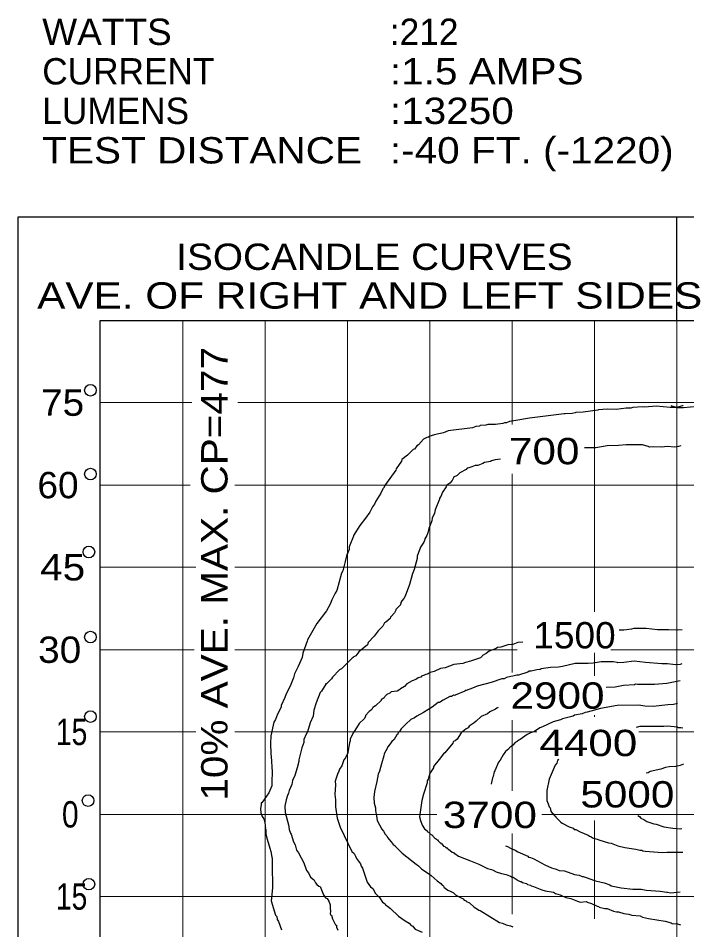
# Model space of a CAD drawing. Extents: x -39.6 to 16.1, y -17.6 to 34.
# Drawn here: x 8.955 to 11.491, y 21.539 to 25 of the extents above; entities that cross this region are included whole.
import ezdxf
from ezdxf.enums import TextEntityAlignment as Align

# ---------------------------------------------------------------- set-up
doc = ezdxf.new("R2010")
doc.units = 0
doc.header["$LTSCALE"] = 0.05
doc.layers.add('1', color=7, linetype='Continuous', lineweight=13)

msp = doc.modelspace()

# ---------------------------------------------------------------- linework, layer by layer
at = {"layer": '1', "lineweight": 25}
for p, q in [((8.95479, 19.45842), (8.95479, 24.24542)), ((8.95479, 24.24542), (13.95379, 24.24542)), ((11.45379, 23.85242), (11.45379, 24.24542)), ((9.26579, 19.78942), (9.26579, 23.85242)), ((9.26579, 23.85242), (13.95379, 23.85242))]:
    msp.add_line(p, q, dxfattribs=at)
at = {"layer": '1'}
for p, q in [((9.57879, 19.78942), (9.57879, 23.85242)), ((9.89179, 19.78942), (9.89179, 23.85242)), ((10.20379, 19.78942), (10.20379, 23.85242)), ((10.51679, 19.78942), (10.51679, 23.85242)), ((10.82879, 23.45742), (10.82879, 23.85242)), ((11.14179, 22.74642), (11.14179, 23.85242)), ((11.45379, 19.78942), (11.45379, 23.85242)), ((9.26579, 23.54042), (9.61279, 23.54042)), ((9.78779, 23.54042), (13.95379, 23.54042)), ((10.82879, 22.51542), (10.82879, 23.27042)), ((9.26579, 23.22742), (9.60679, 23.22742)), ((9.77679, 23.22742), (13.42879, 23.22742)), ((9.26579, 22.91542), (9.62879, 22.91542)), ((9.77679, 22.91542), (13.44479, 22.91542)), ((9.26579, 22.60242), (9.62279, 22.60242)), ((9.77679, 22.60242), (10.84779, 22.60242)), ((11.20379, 22.60242), (13.43979, 22.60242)), ((11.14179, 22.50342), (11.14179, 22.59042)), ((10.82879, 22.06642), (10.82879, 22.33542)), ((11.14179, 22.34742), (11.14179, 22.35342)), ((9.26579, 22.29042), (9.62879, 22.29042)), ((9.77679, 22.29042), (10.92279, 22.29042)), ((11.30979, 22.29042), (13.42879, 22.29042)), ((9.26579, 21.97742), (10.54279, 21.97742)), ((10.94179, 21.97742), (13.43979, 21.97742)), ((11.14179, 21.58042), (11.14179, 21.95442)), ((10.82879, 21.59842), (10.82879, 21.90442)), ((9.26579, 21.66542), (13.43979, 21.66542))]:
    msp.add_line(p, q, dxfattribs=at)
at = {"layer": '1', "lineweight": 25}
for points in [[(11.47579, 23.53042), (11.47479, 23.52842), (11.45179, 23.52242), (11.42879, 23.52142), (11.37579, 23.52742), (11.33179, 23.52342), (11.32279, 23.52442), (11.28679, 23.52142), (11.27879, 23.51942), (11.26179, 23.51942), (11.22279, 23.51442), (11.18879, 23.51542), (11.15579, 23.51342), (11.15379, 23.51142), (11.09779, 23.50442), (11.07079, 23.50342), (11.06779, 23.50142), (11.05679, 23.49942), (11.02979, 23.49842), (11.02579, 23.49742), (10.89479, 23.48142), (10.84279, 23.47242), (10.81879, 23.46942), (10.80679, 23.46442), (10.79979, 23.46442), (10.79379, 23.46142), (10.76579, 23.45742), (10.73679, 23.45742), (10.72879, 23.45442), (10.70679, 23.45342), (10.70479, 23.45142), (10.69079, 23.44942), (10.67879, 23.44542), (10.58579, 23.43342), (10.56779, 23.42642), (10.53279, 23.41842), (10.53079, 23.41642), (10.51679, 23.41342), (10.51079, 23.40942), (10.50479, 23.40842), (10.49179, 23.40142), (10.47379, 23.38042), (10.46679, 23.37642), (10.45779, 23.36442), (10.45379, 23.36242), (10.43179, 23.34142), (10.41079, 23.32442), (10.40879, 23.31842), (10.38879, 23.28942), (10.38779, 23.28442), (10.34779, 23.22942), (10.34079, 23.21542), (10.33779, 23.21342), (10.33079, 23.19642), (10.31179, 23.16642), (10.30679, 23.15542), (10.29879, 23.14542), (10.28879, 23.12442), (10.27179, 23.10142), (10.25079, 23.07342), (10.22679, 23.03642), (10.22679, 23.03342), (10.21079, 22.99242), (10.20979, 22.98342), (10.20379, 22.96742), (10.20179, 22.96442), (10.19579, 22.93742), (10.18579, 22.90142), (10.18179, 22.89342), (10.16379, 22.82742), (10.15779, 22.81742), (10.14479, 22.79142), (10.13879, 22.77542), (10.12379, 22.75042), (10.08779, 22.70242), (10.05279, 22.63942), (10.05079, 22.63442), (10.03479, 22.58942), (10.03179, 22.57342), (10.01679, 22.53842), (10.00279, 22.51042), (9.99879, 22.49542), (9.98679, 22.46442), (9.97079, 22.43542), (9.96679, 22.42142), (9.95279, 22.39042), (9.95279, 22.38442), (9.93879, 22.35742), (9.93079, 22.33742), (9.92479, 22.32742), (9.91379, 22.27542), (9.91179, 22.24742), (9.91379, 22.20542), (9.91479, 22.19642), (9.91779, 22.13842), (9.91679, 22.10142), (9.91679, 22.08542), (9.90579, 22.05942), (9.87879, 22.02142), (9.87679, 22.02142), (9.87679, 22.01342)], [(11.43179, 23.53042), (11.43279, 23.52842), (11.45579, 23.52242), (11.47879, 23.52142), (11.53179, 23.52742)], [(11.46879, 23.37642), (11.45979, 23.37342), (11.44479, 23.37142), (11.41779, 23.37442), (11.39579, 23.37142), (11.36679, 23.37242), (11.34979, 23.37142), (11.34479, 23.37442), (11.32379, 23.38042), (11.26079, 23.38042), (11.23279, 23.37742), (11.18979, 23.37642), (11.14679, 23.36942), (11.10379, 23.36842)], [(10.78479, 23.32542), (10.76379, 23.32342), (10.74979, 23.31942), (10.74679, 23.31642), (10.72379, 23.31342), (10.71779, 23.30942), (10.69879, 23.30242), (10.68879, 23.30242), (10.67579, 23.29642), (10.66379, 23.29342), (10.65779, 23.29142), (10.65479, 23.28642), (10.63079, 23.27442), (10.61979, 23.26342), (10.60679, 23.25742), (10.60679, 23.25442), (10.60179, 23.24442), (10.59179, 23.23442), (10.58079, 23.22742), (10.57879, 23.22142), (10.56479, 23.20042), (10.55879, 23.18442), (10.55279, 23.17742), (10.55279, 23.17442), (10.53679, 23.13342), (10.53379, 23.12142), (10.52479, 23.10242), (10.52379, 23.09142), (10.51279, 23.06242), (10.50879, 23.04642), (10.50479, 23.03542), (10.49779, 23.02342), (10.49679, 23.01742), (10.49379, 23.01042), (10.48079, 22.99142), (10.46879, 22.95742), (10.46779, 22.94842), (10.45679, 22.90642), (10.44879, 22.88842), (10.44879, 22.88642), (10.43979, 22.85042), (10.42279, 22.80542), (10.41779, 22.79642), (10.41079, 22.78842), (10.40579, 22.78142), (10.40479, 22.77342), (10.38779, 22.75542), (10.38779, 22.75242), (10.38279, 22.74242), (10.36979, 22.72842), (10.36679, 22.72742), (10.36579, 22.72142), (10.34979, 22.70642), (10.34479, 22.70442), (10.33779, 22.69242), (10.32879, 22.68242), (10.31979, 22.67442), (10.30579, 22.65342), (10.28279, 22.63042), (10.27979, 22.62142), (10.24679, 22.59442), (10.23579, 22.57942), (10.22579, 22.57442), (10.22579, 22.57242), (10.22179, 22.57042), (10.18079, 22.52942), (10.17379, 22.52642), (10.14679, 22.49842), (10.14279, 22.49242), (10.12479, 22.47342), (10.12079, 22.47342), (10.12179, 22.47142), (10.10579, 22.44442), (10.10079, 22.44042), (10.08479, 22.40042)], [(11.47379, 22.67842), (11.45679, 22.67642), (11.42179, 22.67842), (11.40079, 22.67742), (11.38079, 22.67742), (11.33779, 22.68342), (11.30979, 22.68342), (11.29079, 22.68342), (11.28179, 22.68042), (11.25279, 22.67642), (11.23479, 22.67642)], [(10.86879, 22.63142), (10.85079, 22.62942), (10.83179, 22.62242), (10.81279, 22.62142), (10.78579, 22.61242), (10.77279, 22.61142), (10.76779, 22.60742), (10.74179, 22.59742), (10.73079, 22.58742), (10.71579, 22.58042), (10.71479, 22.57842), (10.70879, 22.57142), (10.67079, 22.55842), (10.65179, 22.55442), (10.64179, 22.55042), (10.60779, 22.54642), (10.57479, 22.53342), (10.55679, 22.53142), (10.53279, 22.51942), (10.51779, 22.51642), (10.50979, 22.51042), (10.49779, 22.50742), (10.49679, 22.50542), (10.48479, 22.50142), (10.48179, 22.49842), (10.47279, 22.49542), (10.46679, 22.49142), (10.46379, 22.48942), (10.44979, 22.48442), (10.42879, 22.47242), (10.42079, 22.46242), (10.40479, 22.45442), (10.40279, 22.45142), (10.39279, 22.44542), (10.36979, 22.44242), (10.36479, 22.43742), (10.35279, 22.43242), (10.34579, 22.42542), (10.34279, 22.41942), (10.33579, 22.41442), (10.33179, 22.41342), (10.33179, 22.40942), (10.30979, 22.38942), (10.29979, 22.38342), (10.29579, 22.37542), (10.28979, 22.37042), (10.28679, 22.36742), (10.27179, 22.35242), (10.27179, 22.34942), (10.26679, 22.34042), (10.24879, 22.32242), (10.23179, 22.29542), (10.22579, 22.28642), (10.21479, 22.26242), (10.21479, 22.25642), (10.21179, 22.24842), (10.20479, 22.21342), (10.20479, 22.21042), (10.19679, 22.19142), (10.18979, 22.18442), (10.18279, 22.16142), (10.17379, 22.14942), (10.16979, 22.13742), (10.16679, 22.13342), (10.15879, 22.10742), (10.15679, 22.10342), (10.15879, 22.08942), (10.15579, 22.05242), (10.15879, 22.03242), (10.15879, 22.01742), (10.15879, 22.00542), (10.16479, 21.96242), (10.17679, 21.92842), (10.22079, 21.83642), (10.22879, 21.82842), (10.23479, 21.81842), (10.23779, 21.80942), (10.25279, 21.78942)], [(11.47279, 22.54842), (11.46579, 22.54642), (11.44879, 22.54542), (11.41879, 22.54942), (11.40479, 22.54942), (11.39679, 22.54842), (11.33479, 22.55442), (11.29179, 22.55842), (11.25279, 22.55342), (11.22979, 22.55242), (11.22779, 22.55442), (11.21379, 22.55642), (11.19679, 22.55642), (11.16679, 22.55642), (11.13579, 22.55142), (11.11679, 22.55042), (11.11479, 22.55042), (11.06779, 22.55042), (11.01979, 22.53842), (11.00479, 22.53642), (10.97379, 22.53542), (10.93879, 22.52942), (10.93479, 22.52742), (10.92179, 22.52642), (10.91679, 22.52442), (10.90079, 22.52042), (10.89379, 22.52042), (10.88879, 22.51742), (10.85279, 22.50642), (10.84679, 22.50642), (10.83079, 22.50242), (10.82379, 22.50042), (10.80679, 22.49642), (10.79879, 22.49242), (10.78979, 22.49142), (10.74879, 22.47742), (10.69579, 22.46342), (10.67779, 22.45642), (10.65479, 22.44742), (10.65079, 22.44742), (10.64979, 22.44542), (10.61279, 22.43042), (10.61079, 22.42842), (10.60679, 22.42942), (10.59879, 22.42442), (10.59279, 22.42442), (10.56679, 22.41142), (10.55279, 22.40242), (10.54779, 22.40142), (10.52479, 22.38442), (10.49279, 22.36442), (10.46679, 22.35042), (10.45879, 22.34342), (10.44379, 22.33742), (10.42479, 22.31942), (10.40779, 22.30142), (10.40179, 22.29142), (10.39679, 22.28742), (10.39479, 22.28142), (10.39179, 22.27942), (10.38079, 22.26142), (10.37279, 22.25442), (10.35879, 22.23442), (10.35579, 22.23242), (10.35579, 22.23042), (10.34279, 22.20742), (10.34179, 22.19942), (10.33279, 22.16942), (10.32579, 22.14142), (10.32079, 22.13042), (10.31479, 22.10242), (10.30679, 22.06442), (10.30379, 22.04142), (10.30579, 22.01942), (10.30979, 22.00242), (10.30979, 21.99142), (10.31279, 21.97642), (10.31379, 21.97142), (10.31679, 21.95342), (10.33379, 21.92142), (10.34079, 21.91342), (10.34679, 21.90242), (10.35279, 21.89642), (10.35579, 21.88942), (10.36979, 21.87242), (10.37779, 21.86242), (10.38479, 21.85842), (10.38479, 21.85642), (10.41179, 21.83042), (10.46479, 21.78842), (10.46879, 21.78542), (10.47379, 21.78242), (10.48479, 21.77042), (10.51679, 21.74842), (10.52179, 21.74542), (10.54379, 21.72442), (10.55879, 21.71442), (10.56279, 21.70842), (10.56779, 21.70542), (10.56979, 21.70042), (10.58479, 21.68942)], [(11.46579, 22.48442), (11.41579, 22.47442), (11.36879, 22.47042), (11.30379, 22.47042), (11.29679, 22.47142), (11.29279, 22.46942), (11.25079, 22.46642), (11.21979, 22.46042), (11.18579, 22.45942)], [(10.08479, 22.40042), (10.07679, 22.37342), (10.07379, 22.35042), (10.06279, 22.32542), (10.05179, 22.29042), (10.04779, 22.28142), (10.03879, 22.26142), (10.03779, 22.25042), (10.03079, 22.23042), (10.01979, 22.18442), (10.01979, 22.17742), (10.01279, 22.15342), (10.00379, 22.12542), (9.99579, 22.10642), (9.99279, 22.09042), (9.98279, 22.06842), (9.98079, 22.05742), (9.97579, 22.04842), (9.97079, 22.03242), (9.96679, 22.00842), (9.96779, 21.98442), (9.98079, 21.93742), (9.98279, 21.91942), (9.98779, 21.90542), (9.99079, 21.90242), (9.99879, 21.87342), (10.00579, 21.86142), (10.01079, 21.84142), (10.01779, 21.83142), (10.03779, 21.79342), (10.04879, 21.76442), (10.05579, 21.75542), (10.06379, 21.73842), (10.07479, 21.73042), (10.07679, 21.73042), (10.08279, 21.71742), (10.08779, 21.71042), (10.09579, 21.70442), (10.09979, 21.70342), (10.11279, 21.67242), (10.12079, 21.66042), (10.12679, 21.65842), (10.13379, 21.64742), (10.13879, 21.63342), (10.13779, 21.62142), (10.13979, 21.61042), (10.13879, 21.59942), (10.14079, 21.59442), (10.14279, 21.59442), (10.14679, 21.58042), (10.15879, 21.55742), (10.16179, 21.55642), (10.16279, 21.54842), (10.16779, 21.53742)], [(11.45579, 22.39842), (11.45079, 22.39742), (11.44079, 22.39442), (11.41979, 22.39342), (11.36379, 22.38742), (11.33179, 22.38842), (11.30879, 22.39142), (11.22779, 22.39042), (11.16379, 22.37942), (11.11379, 22.36542), (11.10579, 22.36442), (11.09379, 22.35842), (11.06579, 22.35342), (11.06079, 22.35042), (11.01979, 22.33942), (11.01179, 22.33642), (10.98379, 22.32842), (10.94379, 22.30942), (10.93379, 22.30642), (10.91379, 22.29242), (10.89779, 22.28642), (10.88579, 22.28042), (10.85979, 22.26142), (10.85379, 22.25942), (10.84779, 22.25342), (10.84079, 22.25042), (10.83179, 22.23942), (10.82379, 22.23342), (10.81879, 22.23142), (10.81579, 22.22642), (10.80379, 22.21542), (10.79479, 22.20342), (10.78379, 22.18342), (10.77679, 22.17542), (10.76279, 22.14242), (10.76079, 22.13842), (10.75679, 22.12142), (10.75379, 22.11642), (10.74879, 22.09242)], [(10.77579, 22.38242), (10.77079, 22.38042), (10.76579, 22.37642), (10.74379, 22.36642), (10.73479, 22.35942), (10.71179, 22.34842), (10.69179, 22.33142), (10.68479, 22.32542), (10.66579, 22.31242), (10.66179, 22.30642), (10.65479, 22.30242), (10.63579, 22.28642), (10.61979, 22.26342), (10.61279, 22.25642), (10.60679, 22.25342), (10.60479, 22.25242), (10.60379, 22.24742), (10.57279, 22.21042), (10.56779, 22.20742), (10.55179, 22.18542), (10.53079, 22.15942), (10.52979, 22.15442), (10.52079, 22.13842), (10.51479, 22.13142), (10.50979, 22.11142), (10.50679, 22.10442), (10.50579, 22.09642), (10.49179, 22.05442), (10.48579, 22.03042), (10.47779, 21.96842), (10.48079, 21.95442), (10.48679, 21.93642), (10.49579, 21.92242), (10.50579, 21.91442), (10.50579, 21.91242), (10.51479, 21.90742), (10.51679, 21.90442), (10.51879, 21.90242), (10.52379, 21.89942), (10.53379, 21.88842), (10.54179, 21.88342), (10.54379, 21.88042), (10.54579, 21.88042), (10.54779, 21.87642), (10.55479, 21.87042), (10.55679, 21.87042), (10.55879, 21.86642), (10.56179, 21.86542), (10.56879, 21.85642), (10.57279, 21.85542), (10.57679, 21.85142), (10.57979, 21.85142), (10.58279, 21.84742), (10.58779, 21.84542), (10.60179, 21.83342), (10.60579, 21.83242), (10.60879, 21.82842), (10.61079, 21.82842), (10.62479, 21.81842), (10.67079, 21.80142), (10.70179, 21.78842), (10.73479, 21.77142), (10.74979, 21.76742), (10.75679, 21.76542), (10.76779, 21.75942), (10.78879, 21.75242), (10.80579, 21.74942), (10.81879, 21.74442), (10.82279, 21.74242), (10.82879, 21.73942), (10.83279, 21.73942), (10.85179, 21.72642), (10.85979, 21.72242), (10.86279, 21.72242), (10.86779, 21.71842), (10.88279, 21.71542), (10.88679, 21.71142), (10.89879, 21.70842)], [(11.47579, 22.30442), (11.46879, 22.30642), (11.45879, 22.30642), (11.45579, 22.30842), (11.41879, 22.31242), (11.40479, 22.31042), (11.31379, 22.31042), (11.29879, 22.30742)], [(11.00579, 22.18542), (11.00079, 22.18242), (10.99779, 22.17142), (10.99179, 22.16442), (10.96979, 22.11042), (10.95979, 22.06742), (10.96079, 22.02942), (10.96579, 22.01742), (10.96979, 22.00642), (10.97279, 22.00242), (10.97579, 21.98942), (10.98079, 21.98242), (10.98579, 21.97942), (10.98879, 21.97342), (10.99379, 21.97042), (10.99479, 21.96642), (11.01379, 21.94742), (11.01879, 21.94442), (11.04479, 21.93042), (11.05979, 21.92442), (11.06379, 21.92042), (11.06979, 21.91942), (11.08679, 21.91042), (11.11779, 21.89842), (11.12279, 21.89442), (11.12779, 21.89342), (11.13379, 21.88842), (11.15479, 21.88142), (11.15779, 21.88042), (11.19379, 21.86942), (11.20479, 21.86742), (11.22979, 21.85842), (11.25679, 21.85142), (11.29779, 21.84542), (11.31379, 21.84142), (11.32079, 21.84142), (11.32479, 21.83942), (11.33379, 21.83742), (11.39979, 21.83242), (11.41679, 21.83342), (11.47679, 21.83342)], [(11.47879, 22.16742), (11.46679, 22.16242), (11.44979, 22.15842), (11.42479, 22.15742), (11.41079, 22.15542), (11.39279, 22.14942), (11.35279, 22.13942), (11.34479, 22.13442), (11.33679, 22.13342)], [(9.87679, 22.01342), (9.87379, 21.99942), (9.87579, 21.98342), (9.88079, 21.96942), (9.88679, 21.96042), (9.89079, 21.94742), (9.89179, 21.93242), (9.89279, 21.92742), (9.89179, 21.92542), (9.89379, 21.91942), (9.89479, 21.90242), (9.89979, 21.88342), (9.90879, 21.84842), (9.91379, 21.83642), (9.91679, 21.81442), (9.91879, 21.81042), (9.91779, 21.78742), (9.91979, 21.69842), (9.91479, 21.64842), (9.93079, 21.59442), (9.93579, 21.58942), (9.93779, 21.57842), (9.94279, 21.57042), (9.95379, 21.53842)], [(11.30579, 21.97342), (11.31179, 21.96942), (11.31679, 21.96342), (11.32779, 21.95842), (11.33979, 21.95042), (11.36679, 21.94142), (11.37479, 21.94042), (11.40479, 21.92942), (11.43779, 21.92442), (11.46779, 21.92242), (11.47279, 21.92342)], [(10.80379, 21.85842), (10.81079, 21.85542), (10.82279, 21.84842), (10.84079, 21.84142), (10.84979, 21.83542), (10.88879, 21.81842), (10.89079, 21.81542), (10.89879, 21.81342), (10.91079, 21.80842), (10.95279, 21.78542), (10.97779, 21.77442), (10.99579, 21.76942), (11.00679, 21.76442), (11.02779, 21.76242), (11.06479, 21.74842), (11.08279, 21.74642), (11.09379, 21.74142), (11.09779, 21.74142), (11.11679, 21.73542), (11.11979, 21.73442), (11.14479, 21.72542), (11.17779, 21.71742), (11.19979, 21.70942), (11.20479, 21.70642), (11.24279, 21.69842), (11.28679, 21.69342), (11.31879, 21.69342), (11.33779, 21.68942), (11.38979, 21.68542), (11.41579, 21.68142), (11.41779, 21.68142), (11.42979, 21.67942), (11.46679, 21.68342)], [(10.25279, 21.78942), (10.25579, 21.78042), (10.26079, 21.77342), (10.26979, 21.74642), (10.27879, 21.72042), (10.29079, 21.70242), (10.29979, 21.69542), (10.31079, 21.67742), (10.32579, 21.66142), (10.33679, 21.64442), (10.34679, 21.63742), (10.34879, 21.63442), (10.35579, 21.62842), (10.36779, 21.61942), (10.39779, 21.59142), (10.42279, 21.57342), (10.43779, 21.56442), (10.44579, 21.55542), (10.45379, 21.55242), (10.45379, 21.55042), (10.46079, 21.54142), (10.48679, 21.53042)], [(10.89879, 21.70842), (10.90079, 21.70542), (10.90979, 21.70342), (10.94079, 21.69042), (10.95379, 21.68642), (10.98579, 21.68142), (10.99379, 21.67642), (11.01079, 21.67142), (11.03279, 21.66142), (11.05079, 21.65842), (11.07679, 21.64742), (11.08679, 21.64442), (11.11079, 21.64642), (11.11279, 21.64442), (11.12979, 21.63942), (11.15179, 21.62842), (11.15779, 21.62742), (11.15879, 21.62542), (11.17979, 21.61942), (11.18979, 21.61942), (11.21279, 21.61042), (11.22479, 21.60742), (11.23179, 21.60742), (11.25279, 21.60142), (11.26179, 21.59942), (11.27179, 21.59842), (11.28279, 21.59442), (11.31479, 21.59242), (11.32279, 21.58742), (11.34579, 21.58242), (11.40879, 21.57142), (11.43179, 21.56542), (11.43579, 21.56342), (11.45579, 21.56142), (11.46779, 21.55842)], [(10.58479, 21.68942), (10.60479, 21.68042), (10.61379, 21.67242), (10.62579, 21.66542), (10.64279, 21.65642), (10.64679, 21.65142), (10.65379, 21.64942), (10.65579, 21.64642), (10.66679, 21.64142), (10.68479, 21.62542), (10.69779, 21.61742), (10.70279, 21.61342), (10.70679, 21.61242), (10.78079, 21.56642), (10.79179, 21.56442), (10.80579, 21.55742), (10.82279, 21.55442), (10.83079, 21.55042)]]:
    msp.add_lwpolyline(points, dxfattribs=at)
for centre in [(9.22879, 23.58742), (9.22879, 23.26942), (9.22279, 22.97342), (9.22879, 22.65042), (9.22879, 22.34842), (9.21979, 22.02942), (9.22279, 21.71242)]:
    msp.add_circle(centre, 0.022, dxfattribs=at)

# ---------------------------------------------------------------- texts
at = {"layer": '1'}
for s, width, p in [('WATTS', 1.05, (9.04579, 24.89842)), (':1.5 AMPS', 1.15, (10.36479, 24.74842)), (':13250', 1.15, (10.36479, 24.59842)), ('TEST DISTANCE', 1.15, (9.04579, 24.44842)), (':-40 FT. (-1220)', 1.15, (10.36479, 24.44842))]:
    msp.add_text(s, height=0.1, dxfattribs=dict(at, width=width)).set_placement(p)
for s, p in [(':212', (10.36479, 24.89842)), ('CURRENT', (9.04579, 24.74842)), ('LUMENS', (9.04579, 24.59842))]:
    msp.add_text(s, height=0.1, dxfattribs=at).set_placement(p)
for s, width, p in [('ISOCANDLE CURVES', 1.1, (10.30629, 24.04442)), ('AVE. OF RIGHT AND LEFT SIDES', 1.2, (10.28829, 23.89742)), ('700', 1.2, (10.95029, 23.30642)), ('1500', 1.05, (11.06529, 22.60742)), ('2900', 1.2, (11.00079, 22.37842)), ('4400', 1.25, (11.11779, 22.19842)), ('5000', 1.2, (11.26579, 22.00342)), ('3700', 1.2, (10.74429, 21.92542))]:
    msp.add_text(s, height=0.1, dxfattribs=dict(at, width=width)).set_placement(p, align=Align.CENTER)
at = {"layer": '1', "width": 1.15}
msp.add_text('10% AVE. MAX. CP=477', height=0.1, rotation=90, dxfattribs=at).set_placement((9.74879, 22.02942))
at = {"layer": '1'}
for s, width, p in [('75', 1.1, (9.20479, 23.49042)), ('60', 1.05, (9.18379, 23.17742)), ('45', 1.15, (9.20879, 22.86542)), ('30', 1.1, (9.19379, 22.55242)), ('15', 0.8, (9.21679, 22.24042)), ('0', 0.85, (9.18379, 21.92742)), ('15', 0.8, (9.21679, 21.61542))]:
    msp.add_text(s, height=0.1, dxfattribs=dict(at, width=width)).set_placement(p, align=Align.RIGHT)

doc.saveas('drawing.dxf')
